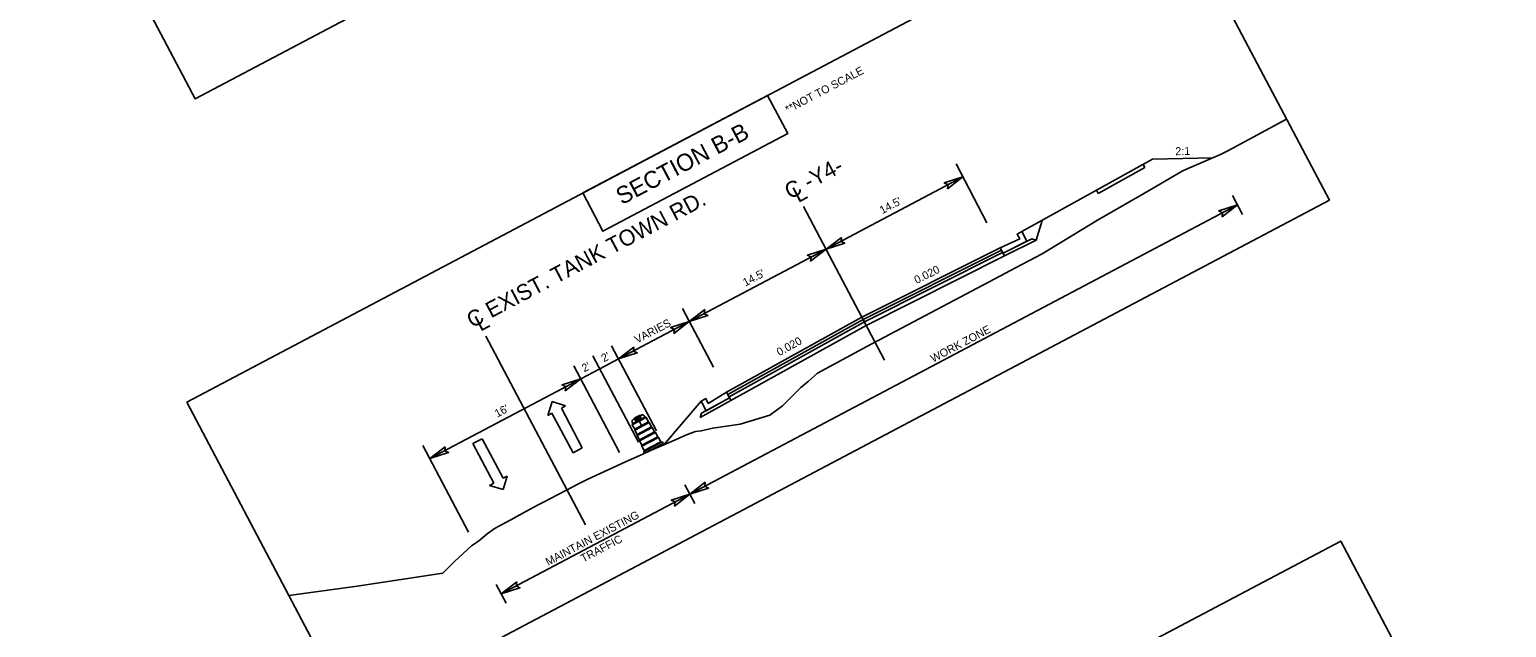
# Model space of a CAD drawing. Extents: x 1487176 to 1495274, y 497106 to 503692.
# Drawn here: x 1488601.9 to 1488740.3, y 497288.5 to 497344.5 of the extents above; entities that cross this region are included whole.
import ezdxf

# ---------------------------------------------------------------- set-up
doc = ezdxf.new("R2010")
doc.units = 0
for name, color, linetype in [('Default', 7, 'Continuous'), ('Exist XS Ground Line', 7, 'Continuous'), ('Prop Terminator CELL', 7, 'Continuous'), ('Typical Hinge Slope Interstate CELL', 7, 'Continuous'), ('WZ OSDR CELL', 7, 'Continuous')]:
    doc.layers.add(name, color=color, linetype=linetype)

msp = doc.modelspace()

# ---------------------------------------------------------------- linework, layer by layer
at = {"layer": 'Default'}
for p, q in [((1488707.17, 497332.33), (1488712.81, 497332.46)), ((1488691.65, 497326.39), (1488688.75, 497331.89)), ((1488706.45, 497331.55), (1488706.3, 497331.85)), ((1488689.39, 497330.67), (1488676.57, 497323.9)), ((1488702.08, 497329.13), (1488701.92, 497329.42)), ((1488715.13, 497328.06), (1488663.81, 497300.95)), ((1488715.6, 497327.17), (1488714.66, 497328.94)), ((1488682.06, 497313.5), (1488674.46, 497327.9)), ((1488676.57, 497323.9), (1488663.75, 497317.13)), ((1488666.01, 497312.85), (1488663.1, 497318.35)), ((1488657.12, 497313.62), (1488663.75, 497317.13)), ((1488654.02, 497298.07), (1488644.68, 497315.76)), ((1488660.68, 497306.87), (1488656.47, 497314.85)), ((1488657.21, 497304.87), (1488652.93, 497312.98)), ((1488658.98, 497305.81), (1488654.7, 497313.92)), ((1488655.35, 497312.69), (1488657.12, 497313.62)), ((1488653.58, 497311.76), (1488639.43, 497304.29)), ((1488653.58, 497311.76), (1488655.35, 497312.69)), ((1488650.89, 497309.62), (1488650.49, 497308.33)), ((1488652.16, 497309.22), (1488650.89, 497309.62)), ((1488651.76, 497309.01), (1488652.16, 497309.22)), ((1488653.72, 497305.29), (1488651.76, 497309.01)), ((1488661.36, 497305.58), (1488664.86, 497309.67)), ((1488650.49, 497308.33), (1488650.88, 497308.54)), ((1488650.88, 497308.54), (1488652.85, 497304.83)), ((1488643.45, 497305.69), (1488644.33, 497306.15)), ((1488644.33, 497306.15), (1488646.29, 497302.44)), ((1488643.06, 497297.4), (1488638.78, 497305.51)), ((1488645.42, 497301.98), (1488643.45, 497305.69)), ((1488652.85, 497304.83), (1488653.72, 497305.29)), ((1488645.02, 497301.77), (1488645.42, 497301.98)), ((1488646.31, 497301.38), (1488645.02, 497301.77)), ((1488646.29, 497302.44), (1488646.69, 497302.65)), ((1488646.69, 497302.65), (1488646.31, 497301.38)), ((1488664.27, 497300.07), (1488663.34, 497301.84)), ((1488663.81, 497300.95), (1488646.12, 497291.62)), ((1488646.59, 497290.73), (1488645.65, 497292.5))]:
    msp.add_line(p, q, dxfattribs=at)
for points in [[(1488601.91, 497367.41), (1488668.76, 497402.7), (1488684.29, 497373.28), (1488617.44, 497337.99)], [(1488616.64, 497309.57), (1488708.21, 497357.92), (1488723.75, 497328.5), (1488632.18, 497280.15)], [(1488653.77, 497329.17), (1488671.08, 497338.31), (1488672.98, 497334.73), (1488655.66, 497325.59)], [(1488680.05, 497317.31), (1488679.99, 497317.42), (1488679.99, 497317.42), (1488680.05, 497317.31)], [(1488680.05, 497317.31), (1488679.99, 497317.42), (1488679.99, 497317.42), (1488680.05, 497317.31)], [(1488657.96, 497261.26), (1488724.81, 497296.56), (1488740.34, 497267.13), (1488673.49, 497231.84)]]:
    msp.add_lwpolyline(points, close=True, dxfattribs=at)
for points in [[(1488694.92, 497325.55), (1488707.17, 497332.33), (1488712.81, 497332.46)], [(1488702.08, 497329.13), (1488706.45, 497331.55)], [(1488693.3, 497323.27), (1488696.25, 497324.75), (1488696.82, 497326.59)], [(1488692.89, 497324.04), (1488694.72, 497324.87), (1488694.48, 497325.31), (1488694.92, 497325.55)], [(1488694.92, 497325.55), (1488695.4, 497324.65), (1488693.16, 497323.53)], [(1488694.72, 497324.87), (1488694.48, 497325.31), (1488694.92, 497325.55)], [(1488679.93, 497317.53), (1488692.89, 497324.04)], [(1488679.93, 497317.53), (1488692.89, 497324.04)], [(1488680.05, 497317.31), (1488693.01, 497323.82)], [(1488693.01, 497323.82), (1488680.05, 497317.31)], [(1488692.89, 497324.04), (1488694.72, 497324.87)], [(1488693.16, 497323.53), (1488692.89, 497324.04)], [(1488692.89, 497324.04), (1488693.01, 497323.82)], [(1488693.01, 497323.82), (1488693.12, 497323.6)], [(1488693.16, 497323.53), (1488695.84, 497324.87), (1488696.25, 497324.75)], [(1488696.25, 497324.75), (1488693.3, 497323.27)], [(1488693.12, 497323.6), (1488680.17, 497317.09)], [(1488680.17, 497317.09), (1488693.12, 497323.6)], [(1488693.3, 497323.27), (1488680.34, 497316.76)], [(1488680.34, 497316.76), (1488693.3, 497323.27)], [(1488693.12, 497323.6), (1488693.3, 497323.27)], [(1488693.3, 497323.27), (1488693.16, 497323.53)], [(1488679.93, 497317.53), (1488667.25, 497310.5)], [(1488679.93, 497317.53), (1488667.25, 497310.5)], [(1488680.05, 497317.31), (1488667.36, 497310.28)], [(1488667.36, 497310.28), (1488680.05, 497317.31)], [(1488667.48, 497310.06), (1488680.17, 497317.09)], [(1488680.17, 497317.09), (1488667.48, 497310.06)], [(1488680.05, 497317.31), (1488679.93, 497317.53)], [(1488680.05, 497317.31), (1488679.93, 497317.53)], [(1488680.17, 497317.09), (1488680.05, 497317.31)], [(1488680.17, 497317.09), (1488680.05, 497317.31)], [(1488680.34, 497316.76), (1488680.17, 497317.09)], [(1488680.34, 497316.76), (1488680.17, 497317.09)], [(1488667.65, 497309.73), (1488680.34, 497316.76)], [(1488680.34, 497316.76), (1488667.65, 497309.73)], [(1488667.52, 497309.99), (1488664.89, 497308.53), (1488664.77, 497308.13)], [(1488667.25, 497310.5), (1488665.53, 497309.46), (1488665.3, 497309.9), (1488664.86, 497309.67)], [(1488664.86, 497309.67), (1488665.33, 497308.77), (1488667.52, 497309.99)], [(1488667.25, 497310.5), (1488665.53, 497309.46)], [(1488667.52, 497309.99), (1488667.25, 497310.5)], [(1488667.25, 497310.5), (1488667.36, 497310.28)], [(1488667.36, 497310.28), (1488667.48, 497310.06)], [(1488667.48, 497310.06), (1488667.65, 497309.73)], [(1488667.65, 497309.73), (1488667.52, 497309.99)], [(1488664.77, 497308.13), (1488667.65, 497309.73)], [(1488665.53, 497309.46), (1488665.3, 497309.9), (1488664.86, 497309.67)]]:
    msp.add_lwpolyline(points, dxfattribs=at)
at = {"layer": 'Exist XS Ground Line'}
msp.add_lwpolyline([(1488626.2, 497291.47), (1488632.61, 497292.34), (1488640.64, 497293.54), (1488641.74, 497294.65), (1488643.34, 497296.12), (1488643.98, 497296.56), (1488644.81, 497297.24), (1488645.56, 497297.76), (1488646.48, 497298.27), (1488647.01, 497298.56), (1488648.42, 497299.32), (1488649.59, 497299.95), (1488650.02, 497300.18), (1488650.74, 497300.55), (1488652.17, 497301.3), (1488653.42, 497301.94), (1488654.1, 497302.29), (1488655.05, 497302.73), (1488656.54, 497303.42), (1488657.44, 497303.84), (1488659.45, 497304.74), (1488660.12, 497305.04), (1488661.15, 497305.48), (1488662.8, 497306.21), (1488663.34, 497306.44), (1488663.89, 497306.66), (1488664.33, 497306.83), (1488664.87, 497306.88), (1488665.94, 497307.15), (1488668.52, 497307.51), (1488671.3, 497308.36), (1488672.5, 497309.24), (1488674.21, 497310.94), (1488674.89, 497311.5), (1488675.76, 497312.29), (1488678.48, 497313.76), (1488680.38, 497314.79), (1488692.39, 497321.14), (1488694.31, 497322.17), (1488696.82, 497323.48), (1488702.02, 497326.62), (1488706.41, 497329.16), (1488709.96, 497331.2), (1488710.42, 497331.44), (1488713.54, 497332.77), (1488714.22, 497333.13), (1488719.74, 497336.09)], dxfattribs=at)
at = {"layer": 'Prop Terminator CELL'}
for points in [[(1488687.95, 497329.55), (1488689.39, 497330.67), (1488687.64, 497330.11), (1488688, 497329.93)], [(1488713.68, 497326.94), (1488715.13, 497328.06), (1488713.38, 497327.49), (1488713.73, 497327.32)], [(1488675.12, 497322.78), (1488676.57, 497323.9), (1488674.82, 497323.34), (1488675.17, 497323.16)], [(1488678.02, 497325.01), (1488676.57, 497323.9), (1488678.32, 497324.46), (1488677.97, 497324.63)], [(1488662.3, 497316.01), (1488663.75, 497317.13), (1488662, 497316.56), (1488662.35, 497316.39)], [(1488665.2, 497318.24), (1488663.75, 497317.13), (1488665.5, 497317.69), (1488665.15, 497317.86)], [(1488658.56, 497314.74), (1488657.12, 497313.62), (1488658.87, 497314.19), (1488658.51, 497314.36)], [(1488652.13, 497310.64), (1488653.58, 497311.76), (1488651.83, 497311.19), (1488652.18, 497311.02)], [(1488640.88, 497305.4), (1488639.43, 497304.29), (1488641.18, 497304.85), (1488640.83, 497305.02)], [(1488665.25, 497302.07), (1488663.81, 497300.95), (1488665.56, 497301.52), (1488665.2, 497301.69)], [(1488662.36, 497299.84), (1488663.81, 497300.95), (1488662.06, 497300.39), (1488662.41, 497300.22)], [(1488647.57, 497292.73), (1488646.12, 497291.62), (1488647.87, 497292.18), (1488647.52, 497292.35)]]:
    msp.add_lwpolyline(points, close=True, dxfattribs=at)
at = {"layer": 'WZ OSDR CELL'}
for p, q in [((1488658.47, 497307.58), (1488658.4, 497307.71)), ((1488658.41, 497307.46), (1488659.71, 497308.15)), ((1488658.41, 497307.46), (1488658.63, 497307.05)), ((1488658.47, 497307.58), (1488659.58, 497308.17)), ((1488658.63, 497307.05), (1488659.93, 497307.73)), ((1488658.63, 497306.96), (1488659.99, 497307.68)), ((1488658.65, 497307.9), (1488658.65, 497307.9)), ((1488658.85, 497306.54), (1488660.21, 497307.26)), ((1488658.86, 497306.46), (1488660.28, 497307.21)), ((1488659.21, 497308.19), (1488659.2, 497308.2)), ((1488659.58, 497308.17), (1488659.51, 497308.3)), ((1488659.71, 497308.15), (1488659.93, 497307.73)), ((1488659.93, 497307.73), (1488659.99, 497307.68)), ((1488659.99, 497307.68), (1488660.21, 497307.26)), ((1488660.21, 497307.26), (1488660.28, 497307.21)), ((1488660.28, 497307.21), (1488660.5, 497306.79)), ((1488658.63, 497307.05), (1488658.63, 497306.96)), ((1488658.63, 497306.96), (1488658.85, 497306.54)), ((1488658.85, 497306.54), (1488658.86, 497306.46)), ((1488658.86, 497306.46), (1488659.08, 497306.04)), ((1488659.08, 497306.04), (1488660.5, 497306.79)), ((1488659.08, 497305.96), (1488660.57, 497306.74)), ((1488659.08, 497306.04), (1488659.08, 497305.96)), ((1488659.08, 497305.96), (1488659.3, 497305.54)), ((1488659.3, 497305.54), (1488660.79, 497306.33)), ((1488659.31, 497305.46), (1488660.86, 497306.27)), ((1488659.52, 497304.95), (1488661.15, 497305.81)), ((1488659.53, 497305.04), (1488661.07, 497305.86)), ((1488660.5, 497306.79), (1488660.57, 497306.74)), ((1488660.57, 497306.74), (1488660.79, 497306.33)), ((1488660.79, 497306.33), (1488660.86, 497306.27)), ((1488660.86, 497306.27), (1488661.07, 497305.86)), ((1488661.07, 497305.86), (1488661.14, 497305.8)), ((1488659.3, 497305.54), (1488659.31, 497305.46)), ((1488659.31, 497305.46), (1488659.53, 497305.04)), ((1488659.53, 497304.77), (1488659.49, 497304.84)), ((1488659.53, 497304.77), (1488661.29, 497305.71)), ((1488659.53, 497305.04), (1488659.53, 497304.95)), ((1488661.29, 497305.71), (1488661.26, 497305.78))]:
    msp.add_line(p, q, dxfattribs=at)
for points in [[(1488658.63, 497306.96), (1488659.31, 497307.32), (1488658.95, 497308.01), (1488658.91, 497307.99), (1488658.89, 497307.98), (1488658.86, 497307.96), (1488658.84, 497307.95), (1488658.81, 497307.93), (1488658.78, 497307.91), (1488658.75, 497307.89), (1488658.73, 497307.87), (1488658.71, 497307.87), (1488658.7, 497307.87), (1488658.69, 497307.87), (1488658.67, 497307.88), (1488658.66, 497307.88), (1488658.66, 497307.89), (1488658.65, 497307.91), (1488658.64, 497307.92), (1488658.64, 497307.94), (1488658.65, 497307.95), (1488658.66, 497307.96), (1488658.67, 497307.97), (1488658.69, 497307.99), (1488658.72, 497308.01), (1488658.79, 497308.06), (1488658.84, 497308.08), (1488658.87, 497308.11), (1488658.89, 497308.12), (1488658.85, 497308.2), (1488658.81, 497308.18), (1488658.76, 497308.16), (1488658.72, 497308.13), (1488658.67, 497308.1), (1488658.63, 497308.07), (1488658.58, 497308.03), (1488658.53, 497307.99), (1488658.5, 497307.96), (1488658.45, 497307.91), (1488658.43, 497307.89), (1488658.41, 497307.88), (1488658.4, 497307.86), (1488658.39, 497307.84), (1488658.38, 497307.82), (1488658.38, 497307.8), (1488658.38, 497307.78), (1488658.38, 497307.75), (1488658.39, 497307.73), (1488658.4, 497307.71), (1488658.47, 497307.58), (1488658.46, 497307.57), (1488658.45, 497307.56), (1488658.44, 497307.54), (1488658.43, 497307.51), (1488658.42, 497307.49), (1488658.41, 497307.46), (1488658.63, 497307.05)], [(1488659.99, 497307.68), (1488659.31, 497307.32), (1488658.95, 497308.01), (1488659.01, 497308.04), (1488659.05, 497308.06), (1488659.08, 497308.08), (1488659.12, 497308.09), (1488659.15, 497308.1), (1488659.18, 497308.11), (1488659.19, 497308.12), (1488659.2, 497308.13), (1488659.21, 497308.14), (1488659.21, 497308.16), (1488659.21, 497308.17), (1488659.21, 497308.18), (1488659.2, 497308.2), (1488659.19, 497308.21), (1488659.18, 497308.22), (1488659.17, 497308.22), (1488659.16, 497308.23), (1488659.15, 497308.22), (1488659.14, 497308.22), (1488659.11, 497308.21), (1488659.09, 497308.2), (1488659.06, 497308.19), (1488659.04, 497308.18), (1488659.01, 497308.17), (1488658.97, 497308.15), (1488658.94, 497308.14), (1488658.92, 497308.13), (1488658.89, 497308.12), (1488658.85, 497308.2), (1488658.89, 497308.22), (1488658.92, 497308.24), (1488658.97, 497308.26), (1488659, 497308.27), (1488659.03, 497308.29), (1488659.07, 497308.3), (1488659.12, 497308.32), (1488659.17, 497308.33), (1488659.23, 497308.35), (1488659.28, 497308.36), (1488659.32, 497308.37), (1488659.34, 497308.38), (1488659.36, 497308.38), (1488659.38, 497308.38), (1488659.4, 497308.38), (1488659.42, 497308.37), (1488659.44, 497308.36), (1488659.45, 497308.35), (1488659.47, 497308.34), (1488659.48, 497308.33), (1488659.5, 497308.31), (1488659.5, 497308.3), (1488659.51, 497308.3), (1488659.58, 497308.17), (1488659.61, 497308.17), (1488659.62, 497308.17), (1488659.64, 497308.16), (1488659.66, 497308.16), (1488659.69, 497308.15), (1488659.7, 497308.15), (1488659.71, 497308.15), (1488659.93, 497307.73)], [(1488658.85, 497306.54), (1488660.21, 497307.26), (1488660.28, 497307.21), (1488660.5, 497306.79), (1488660.57, 497306.74), (1488659.08, 497305.96), (1488659.08, 497306.04), (1488658.86, 497306.46)], [(1488659.3, 497305.54), (1488660.79, 497306.33), (1488660.86, 497306.27), (1488661.07, 497305.86), (1488661.14, 497305.8), (1488661.16, 497305.81), (1488661.17, 497305.82), (1488661.19, 497305.82), (1488661.2, 497305.82), (1488661.21, 497305.81), (1488661.23, 497305.81), (1488661.24, 497305.8), (1488661.25, 497305.79), (1488661.25, 497305.78), (1488661.26, 497305.78), (1488661.29, 497305.71), (1488659.53, 497304.77), (1488659.49, 497304.84), (1488659.49, 497304.85), (1488659.48, 497304.87), (1488659.48, 497304.88), (1488659.48, 497304.89), (1488659.48, 497304.9), (1488659.49, 497304.91), (1488659.5, 497304.93), (1488659.51, 497304.94), (1488659.51, 497304.94), (1488659.52, 497304.95), (1488659.53, 497304.95), (1488659.53, 497305.04), (1488659.31, 497305.46)]]:
    msp.add_lwpolyline(points, close=True, dxfattribs=at)
for centre, radius, start, end in [((1488658.54, 497307.78), 0.157, 134.7843, 207.8351), ((1488658.67, 497307.41), 0.271, 140.1411, 168.3486), ((1488659.67, 497306.64), 1.77, 100.8859, 134.7843), ((1488658.7, 497307.93), 0.0548, 126.5091, 207.8351), ((1488658.7, 497307.92), 0.0548, 207.8351, 305.9838), ((1488659.72, 497306.55), 1.77, 109.1611, 126.5091), ((1488659.77, 497306.45), 1.77, 109.6863, 125.9838), ((1488659.16, 497308.17), 0.0548, 27.8351, 109.1611), ((1488659.16, 497308.16), 0.0548, 289.6863, 27.8351), ((1488659.37, 497308.22), 0.157, 27.8351, 100.8859), ((1488659.6, 497307.9), 0.271, 67.3216, 95.5291), ((1488661.19, 497305.74), 0.0783, 27.8351, 117.8351), ((1488659.56, 497304.88), 0.0783, 117.8351, 207.8351)]:
    msp.add_arc(centre, radius, start, end, dxfattribs=at)

# ---------------------------------------------------------------- texts
at = {"layer": 'Default'}
for s, height, rotation, p in [('**NOT TO SCALE', 0.75, 27.8351, (1488672.98, 497336.6)), ('SECTION B-B', 1.6, 27.8351, (1488657.42, 497328.02)), ('2:1', 0.75, 1.27, (1488709.31, 497332.71)), ("14.5'", 0.75, 27.8351, (1488681.83, 497327.17)), ("14.5'", 0.75, 27.8351, (1488669.01, 497320.4)), ('0.020', 0.75, 26.6893, (1488685.06, 497320.63)), ('VARIES', 0.75, 27.8351, (1488658.86, 497315.04)), ('0.020', 0.75, 28.9809, (1488672.19, 497313.87)), ('WORK ZONE', 0.75, 27.8351, (1488686.61, 497313.27)), ("2'", 0.75, 27.8351, (1488655.74, 497313.3)), ("2'", 0.75, 27.8351, (1488653.91, 497312.36)), ("16'", 0.75, 27.8351, (1488645.75, 497308.12)), ('MAINTAIN EXISTING', 0.75, 27.8351, (1488650.52, 497294.22)), ('TRAFFIC', 0.75, 27.8351, (1488653.81, 497294.54))]:
    msp.add_text(s, height=height, rotation=rotation, dxfattribs=at).set_placement(p)
at = {"layer": 'Typical Hinge Slope Interstate CELL'}
for s, p in [('C -Y4- ', (1488673.18, 497328.54)), ('L', (1488673.96, 497328.22)), ('C EXIST. TANK TOWN RD.', (1488643.39, 497316.48)), ('L', (1488644.17, 497316.16))]:
    msp.add_text(s, height=1.5, rotation=27.8351, dxfattribs=at).set_placement(p)

doc.saveas('drawing.dxf')
